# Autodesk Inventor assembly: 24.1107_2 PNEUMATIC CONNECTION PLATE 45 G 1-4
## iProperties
Created: 2007-06
Part Number: 24.1107_2 PNEUMATIC CONNECTION PLATE 45 G 1-4
Document SubType Name: Assembly
Designer: Andy Moles
Author: Andy Moles
